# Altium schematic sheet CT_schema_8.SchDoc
size 252 x 159 mm
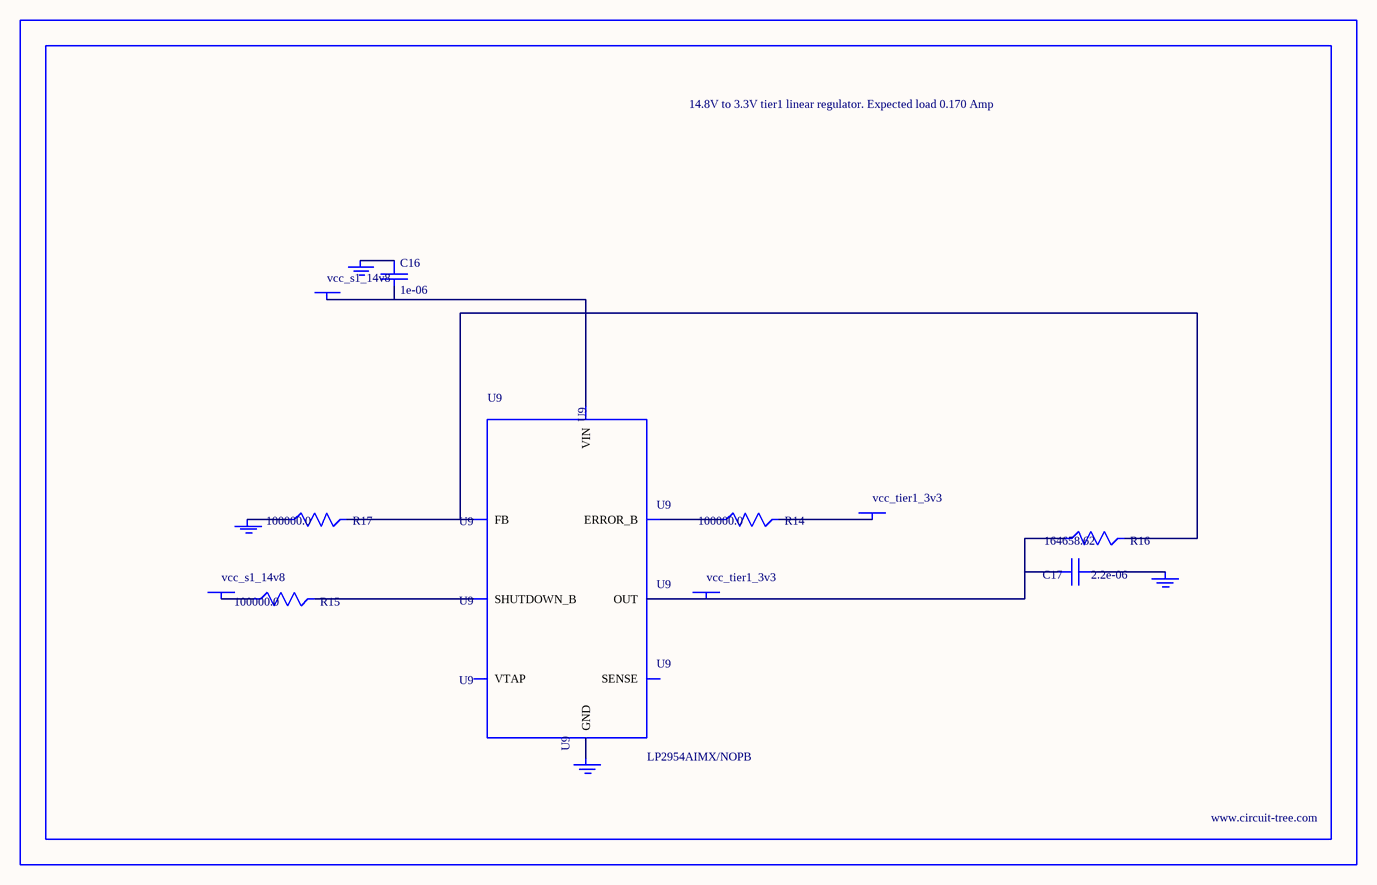
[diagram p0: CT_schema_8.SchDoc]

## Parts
BORDER7  (no value)
C16  1e-06  [EXV-9B]
C17  2.2e-06  [EXV-9B]
GND_INSTANCE_7_0  (no value)
GND_INSTANCE_7_1  (no value)
GND_INSTANCE_7_2  (no value)
GND_INSTANCE_7_3  (no value)
POWER_INSTANCE_7_0  vcc_s1_14v8
POWER_INSTANCE_7_1  vcc_tier1_3v3
POWER_INSTANCE_7_2  vcc_s1_14v8
POWER_INSTANCE_7_3  vcc_tier1_3v3
R14  100000.0  [R0603]
R15  100000.0  [R0603]
R16  164658.62  [R0603]
R17  100000.0  [R0603]
U9  LP2954AIMX/NOPB  [LP2954]

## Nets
NetC16_1: C16.1 GND_INSTANCE_7_2.0(GND)
NetC16_2: C16.2 POWER_INSTANCE_7_2.0(PWR) U9.8(VIN)
NetC17_1: C17.1 GND_INSTANCE_7_0.0(GND)
NetC17_2: C17.2 POWER_INSTANCE_7_3.0(PWR) R16.1 U9.1(OUT)
NetGND_INSTANCE_7_1_0: GND_INSTANCE_7_1.0(GND) R17.1
NetGND_INSTANCE_7_3_0: GND_INSTANCE_7_3.0(GND) U9.4(GND)
NetPOWER_INSTANCE_7_0_0: POWER_INSTANCE_7_0.0(PWR) R15.1
NetPOWER_INSTANCE_7_1_0: POWER_INSTANCE_7_1.0(PWR) R14.2
NetR14_1: R14.1 U9.5(ERROR_B)
NetR15_2: R15.2 U9.3(SHUTDOWN_B)
NetR16_2: R16.2 R17.2 U9.7(FB)

Not connected (* = marked no-connect by the designer): U9 2(SENSE) 6(VTAP)

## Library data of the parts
BORDER7 = BORDER_PAGE7
C16 = EDK105M050A9BAA
C17 = EDK225M050A9BAA
GND_INSTANCE_7_0-GND_INSTANCE_7_3 = GND
POWER_INSTANCE_7_0-POWER_INSTANCE_7_3 = PWR
R14 R15 R17 = RC0603JR-07100KL
R16 = R16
